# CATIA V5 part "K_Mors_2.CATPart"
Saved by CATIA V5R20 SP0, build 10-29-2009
Part number: Mors_2
Bounding box of the stored display mesh (mm): x -950 to -350, y -284.606 to 0, z -215.251 to -81.233
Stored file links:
  G:\Khaled_CFAO_2011\ST2M\ST2M_GR2\jcoetard\Khaled\CAD_CATIA\K_Mors_2.CATPart
  J:\Thinkmotion\Thinkmotion_COETARD\Maquette_catia\Maquette_catia_R20_Licence_education\jcharlescoetard.CATPRODUCT\Assemblage_Pince_Prehension_Mors_Paralleles.CATProduct
  G:\Khaled_CFAO_2011\ST2M\ST2M_GR2\jcoetard\jcoetard\Maquette_jcoetard\Mors.CATPart
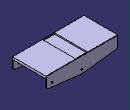
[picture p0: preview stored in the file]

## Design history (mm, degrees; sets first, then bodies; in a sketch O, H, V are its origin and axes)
Set1
  Point1 "Point.9": linked copy from another document
  Point2 "Point.10": linked copy from another document
  Plane1 "Plan_Ref": linked copy from another document
Body1 (main body)
  Sketch1 on Plane1, origin (0, 0, 0), H (-1, 0, 0), V (0, 0, 1)
    line L1 (350, -81.2331) -> (950, -81.2331)
    line L2 (350, -81.2331) -> (350, -162.3278)
    point P3 (350, -179.2511)
    line L3 (950, -81.2331) -> (950, -161.5601)
    point P4 (950, -179.2511)
    construction line L4 (650, -23.3267) -> (650, -331.8394)
    point P7 (650, -81.2331)
    reference projected point E1 (650, -180) from Point2
    line L5 (366.8027, -181.2674) -> (650, -215.2511)
    point P8 (650, -215.2511)
    line L6 (650, -215.2511) -> (932.4351, -181.3589)
    reference projected point E2 (650, -180) from Point2
    reference projected point E3 (400, -150) from Point1
    reference projected point E4 (400, -150) from Point1
    axis line L7 (275.9503, -179.2511) -> (1162.9673, -179.2511)
    arc A1 centre (930.0592, -161.5601) radius 19.9408 from (950, -161.5601) to (932.4351, -181.3589) cw
    arc A2 centre (369.0755, -162.3278) radius 19.0755 from (350, -162.3278) to (366.8027, -181.2674) ccw
    distance L6 E2 = 35
    distance L2 E3 = 50
    distance L5 E4 = 35
    radius A1 = 19.9408
    radius A2 = 19.0755
    horizontal: L1 H, L7 H
    vertical: L2 V, L3 V, L4 V
    coincidence: P7 L4, L4 E1, P8 L4, L7 P4, L7 P3, L3 P4, L6 P4, L2 P3, L5 P3
    midpoint: P7 L1
    tangency: A1 L3, A1 L6, A2 L2, A2 L5
  Pad1: profile Sketch1, direction (0, -1, 0), length 5
  Sketch2 on end face of Pad1, origin (0, -5, 0), H (1, 0, 0), V (0, 0, 1)
    line L1 (-944.7303, -81.2331) -> (-700, -81.2331)
    line L2 (-700, -81.2331) -> (-700, -91.2331)
    line L3 (-700, -91.2331) -> (-600, -91.2331)
    line L4 (-600, -91.2331) -> (-600, -81.2331)
    point P5 (-600, -81.2331)
    line L5 (-600, -81.2331) -> (-350, -81.2331)
    line L6 (-350, -81.2331) -> (-350, -101.2331)
    line L7 (-350, -101.2331) -> (-950, -101.2331)
    line L8 (-950, -101.2331) -> (-950, -81.2331)
    point P9 (-950, -81.2331)
    line L9 (-950, -81.2331) -> (-944.7303, -81.2331)
    axis line L10 (-650, -62.3429) -> (-650, -287.8835)
    reference projected point E1 (-650, -215.2511) from vertex [face of Pad1 from Sketch1.L6 | end face of Pad1 | face of Pad1 from Sketch1.L5]
    reference projected line E2 (-350, -31.2331) -> (-350, -112.3278) from edge [end face of Pad1 | face of Pad1 from Sketch1.L2]
    reference projected line E3 (-950, -111.5601) -> (-950, -31.2331) from edge [end face of Pad1 | face of Pad1 from Sketch1.L3]
    reference projected line E4 (-950, -81.2331) -> (-350, -81.2331) from edge [end face of Pad1 | face of Pad1 from Sketch1.L1]
    distance L10 L4 = 50
    distance L2 L10 = 50
    distance L7 L5 = 20
    length L4 = 10
    horizontal: L1 H, L3 H, L5 H, L7 H, L9 H
    vertical: L2 V, L4 V, L6 V, L8 V, L10 V
    coincidence: P5 L1, P9 L1, L10 E1, L6 E2, L8 E3, L5 E4
  Pad2: profile Sketch2, direction (0, -1, 0), length 274.606
  Sketch3 on start face of Pad1, origin (-370, 0, -150), H (1, 0, 0), V (0, 0, -1)
    point P1 (-30, 0)
    reference projected point E1 (-30, 0) from Point1
    coincidence: E1 P1
  Hole1: placed by Sketch3, at (-400, 0, -150) direction (0, -1, 0), diameter 10, depth 10
  Sketch4 on start face of Pad1, origin (-620, 0, -180), H (1, 0, 0), V (0, 0, -1)
    point P1 (-30, 0)
    reference projected point E1 (-30, 0) from Point2
    coincidence: E1 P1
  Hole2: placed by Sketch4, at (-650, 0, -180) direction (0, -1, 0), diameter 10, depth 10
  Sketch5 on end face of Pad2, origin (0, -279.606, 0), H (1, 0, 0), V (0, 0, 1)
    line L1 (-950, -81.2331) -> (-350, -81.2331)
    point P3 (-650, -215.2511)
    axis line L2 (-1017.4813, -179.2511) -> (-130.4643, -179.2511)
    construction line L3 (-650, -55.7961) -> (-650, -361.4054)
    point P8 (-650, -81.2331)
    reference projected point E1 (-650, -180) from Point2
    line L4 (-950, -81.2331) -> (-950, -157.0717)
    line L5 (-650, -215.2511) -> (-927.9786, -181.8937)
    reference projected line E2 (-650, -215.2511) -> (-932.4351, -181.3589) from edge [end face of Pad1 | face of Pad1 from Sketch1.L6]
    point P9 (-950, -179.2511)
    reference projected line E3 (-950, -161.5601) -> (-950, -81.2331) from edge [end face of Pad1 | face of Pad2]
    line L6 (-650, -215.2511) -> (-372.0214, -181.8937)
    reference projected line E4 (-366.8027, -181.2674) -> (-650, -215.2511) from edge [end face of Pad1 | face of Pad1 from Sketch1.L5]
    reference projected line E5 (-600, -81.2331) -> (-350, -81.2331) from edge [face of Pad2 | end face of Pad2]
    line L7 (-350, -81.2331) -> (-350, -157.0717)
    reference projected line E7 (-350, -81.2331) -> (-350, -162.3278) from edge [end face of Pad1 | face of Pad2]
    point P10 (-350, -179.2511)
    point P11 (-350, -179.2511)
    arc A1 centre (-925, -157.0717) radius 25 from (-950, -157.0717) to (-927.9786, -181.8937) ccw
    arc A2 centre (-375, -157.0717) radius 25 from (-350, -157.0717) to (-372.0214, -181.8937) cw
    radius A1 = 25
    radius A2 = 25
    coincidence: P8 L3, L3 P3, L3 E1, L5 E2, L2 P9, L4 E3, L6 E4, L1 E5, L7 E7, L6 P10, L2 P11, L2 P10, L4 P9, L5 P9, L7 P10, L6 P11
    midpoint: P8 L1
    vertical: L4 V, L7 V
    horizontal: L1 H
    tangency: A1 L4, A1 L5, A2 L7, A2 L6
  Pad3: profile Sketch5, direction (0, -1, 0), length 5
  Sketch6 on end face of Pad3, origin (-650, -284.606, -170), H (1, 0, 0), V (0, 0, 1)
    point P1 (0, -10)
    reference projected point E1 (0, -10) from Point2
    coincidence: E1 P1
  Hole3: placed by Sketch6, at (-650, -284.606, -180) direction (0, 1, 0), diameter 10, depth 10
  Sketch7 on end face of Pad3, origin (-400, -284.606, -140), H (1, 0, 0), V (0, 0, 1)
    point P1 (0, -10)
    reference projected point E1 (0, -10) from Point1
    coincidence: E1 P1
  Hole4: placed by Sketch7, at (-400, -284.606, -150) direction (0, 1, 0), diameter 10, depth 10
  Fillet1: radius 2, on end face of Pad3; end face of Pad1; start face of Pad3; start face of Pad1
